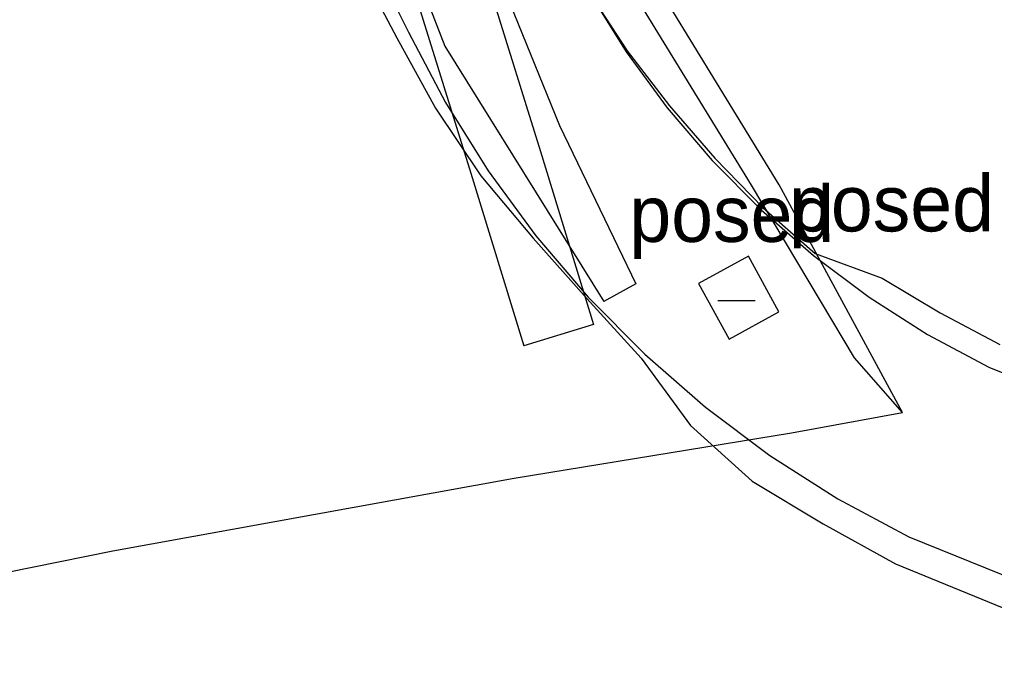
# Model space of a CAD drawing. Extents: x -475575 to -473225, y -1116053 to -1114104.
# Drawn here: x -474375.12 to -474349.11, y -1115076.37 to -1115059.4 of the extents above; entities that cross this region are included whole.
import ezdxf

# ---------------------------------------------------------------- set-up
doc = ezdxf.new("R2010")
doc.units = 0
for name, color, linetype in [('CESTN___P____KOP_N__VRH', 7, 'Continuous'), ('SVK', 7, 'Continuous'), ('Vrstevnice_vedlejsi', 7, 'Continuous'), ('Vrstva_10', 7, 'Continuous')]:
    doc.layers.add(name, color=color, linetype=linetype)

msp = doc.modelspace()

# ---------------------------------------------------------------- linework, layer by layer
at = {"layer": 'CESTN___P____KOP_N__VRH'}
for p, q in [((-474365.634, -1115057.941), (-474364.745, -1115059.732)), ((-474365.981, -1115058.113), (-474365.056, -1115059.887)), ((-474365.056, -1115059.887), (-474364.018, -1115061.759)), ((-474364.745, -1115059.732), (-474363.754, -1115061.607)), ((-474363.754, -1115061.607), (-474362.615, -1115063.428)), ((-474364.018, -1115061.759), (-474362.812, -1115063.561)), ((-474362.615, -1115063.428), (-474361.345, -1115065.16)), ((-474362.812, -1115063.561), (-474361.419, -1115065.219)), ((-474361.419, -1115065.219), (-474359.987, -1115066.828)), ((-474361.345, -1115065.16), (-474359.951, -1115066.794)), ((-474359.987, -1115066.828), (-474358.532, -1115068.419)), ((-474359.951, -1115066.794), (-474358.439, -1115068.319)), ((-474358.532, -1115068.419), (-474357.214, -1115070.218)), ((-474358.439, -1115068.319), (-474356.818, -1115069.728)), ((-474356.818, -1115069.728), (-474355.098, -1115071.014)), ((-474357.214, -1115070.218), (-474355.571, -1115071.699)), ((-474355.098, -1115071.014), (-474353.287, -1115072.169)), ((-474355.571, -1115071.699), (-474353.678, -1115072.835)), ((-474353.287, -1115072.169), (-474351.396, -1115073.186)), ((-474353.678, -1115072.835), (-474351.747, -1115073.901)), ((-474351.396, -1115073.186), (-474347.414, -1115074.789)), ((-474351.747, -1115073.901), (-474347.664, -1115075.573))]:
    msp.add_line(p, q, dxfattribs=at)
for points in [[(-474359.916, -1115058.683), (-474358.934, -1115060.253)], [(-474359.911, -1115058.681), (-474358.905, -1115060.233)], [(-474358.934, -1115060.253), (-474357.839, -1115061.746)], [(-474358.905, -1115060.233), (-474357.777, -1115061.696)], [(-474357.777, -1115061.696), (-474356.565, -1115063.088)], [(-474357.839, -1115061.746), (-474356.637, -1115063.154)], [(-474356.637, -1115063.154), (-474355.334, -1115064.469)], [(-474356.565, -1115063.088), (-474355.282, -1115064.414)], [(-474355.334, -1115064.469), (-474353.937, -1115065.684)], [(-474355.282, -1115064.414), (-474353.892, -1115065.629)], [(-474353.937, -1115065.684), (-474352.454, -1115066.792)], [(-474353.892, -1115065.629), (-474352.105, -1115066.287)], [(-474352.105, -1115066.287), (-474350.555, -1115067.212)], [(-474352.454, -1115066.792), (-474350.893, -1115067.788)], [(-474350.555, -1115067.212), (-474348.962, -1115068.053)], [(-474350.893, -1115067.788), (-474349.262, -1115068.665)], [(-474349.262, -1115068.665), (-474345.829, -1115070.046)]]:
    msp.add_lwpolyline(points, dxfattribs=at)
at = {"layer": 'SVK'}
msp.add_line((-474356.492, -1115066.882), (-474355.492, -1115066.882), dxfattribs=at)
for points in [[(-474531.417, -1114949.964), (-474518.735, -1114954.223), (-474505.508, -1114958.773), (-474490.04, -1114963.316), (-474478.285, -1114966.016), (-474465.065, -1114968.999), (-474452.484, -1114971.31), (-474438.955, -1114973.279), (-474425.793, -1114974.806), (-474414.372, -1114976.092), (-474408.245, -1114977.467), (-474402.318, -1114980.411), (-474397.56, -1114985.161), (-474394.659, -1114990.262), (-474387.875, -1115004.966), (-474382.653, -1115016.529), (-474372.424, -1115037.125), (-474369.444, -1115043.04), (-474363.811, -1115054.608), (-474360.711, -1115062.22), (-474358.674, -1115066.438), (-474359.526, -1115066.91)], [(-474532.059, -1114951.8), (-474519.359, -1114956.065), (-474506.097, -1114960.627), (-474490.531, -1114965.199), (-474478.715, -1114967.913), (-474465.454, -1114970.905), (-474452.799, -1114973.23), (-474439.207, -1114975.208), (-474426.014, -1114976.739), (-474414.695, -1114978.013), (-474408.9, -1114979.313), (-474403.467, -1114982.012), (-474399.12, -1114986.352), (-474396.39, -1114991.152), (-474389.644, -1115005.774), (-474384.41, -1115017.362), (-474374.163, -1115037.995), (-474371.187, -1115043.903), (-474365.624, -1115055.327), (-474363.775, -1115060.104), (-474359.526, -1115066.91)], [(-474354.522, -1115070.413), (-474351.56, -1115069.868), (-474354.851, -1115063.802), (-474360.04, -1115055.335), (-474366.606, -1115042.832), (-474370.618, -1115035.13), (-474372.803, -1115030.873)], [(-474351.56, -1115069.868), (-474352.844, -1115068.409), (-474355.586, -1115063.813), (-474358.809, -1115058.557), (-474361.838, -1115053.994), (-474365.362, -1115048.002), (-474368.068, -1115042.4), (-474370.949, -1115037.299), (-474373.878, -1115031.38)], [(-474456.608, -1115092.439), (-474444.222, -1115089.576), (-474432.477, -1115086.843), (-474420.046, -1115083.62), (-474408.267, -1115081.299), (-474394.218, -1115078.309), (-474384.628, -1115075.984), (-474372.626, -1115073.554), (-474361.918, -1115071.619), (-474354.522, -1115070.413)]]:
    msp.add_lwpolyline(points, dxfattribs=at)
msp.add_lwpolyline([(-474354.857, -1115067.189), (-474355.671, -1115065.704), (-474357.002, -1115066.433), (-474356.187, -1115067.919)], close=True, dxfattribs=at)
at = {"layer": 'Vrstevnice_vedlejsi'}
for points in [[(-474227.218, -1115164.851), (-474226.448, -1115162.426), (-474227.525, -1115159.571), (-474230.451, -1115156.287), (-474235.226, -1115152.573), (-474240.399, -1115148.881), (-474245.971, -1115145.211), (-474251.942, -1115141.562), (-474256.818, -1115137.139), (-474260.6, -1115131.942), (-474263.287, -1115125.971), (-474265.918, -1115121.36), (-474268.492, -1115118.11), (-474271.011, -1115116.221), (-474273.409, -1115112.993), (-474275.686, -1115108.429), (-474277.843, -1115102.526), (-474279.974, -1115096.744), (-474282.078, -1115091.082), (-474284.156, -1115085.541), (-474285.812, -1115080.883), (-474287.047, -1115077.109), (-474287.86, -1115074.218), (-474288.244, -1115068.81), (-474288.198, -1115060.885), (-474287.724, -1115050.442), (-474287.488, -1115042.595), (-474287.491, -1115037.342), (-474287.732, -1115034.684), (-474288.91, -1115029.354), (-474291.024, -1115021.351), (-474294.074, -1115010.675), (-474297.009, -1115000.754), (-474299.828, -1114991.588), (-474302.532, -1114983.176), (-474304.676, -1114975.928), (-474306.261, -1114969.843), (-474307.286, -1114964.921), (-474309.265, -1114957.199), (-474312.198, -1114946.677), (-474316.084, -1114933.354), (-474318.675, -1114924.468), (-474319.971, -1114920.02), (-474319.973, -1114920.01), (-474319.977, -1114919.992), (-474319.984, -1114919.965), (-474319.992, -1114919.931), (-474321.301, -1114916.779), (-474323.911, -1114910.509), (-474327.823, -1114901.121), (-474333.571, -1114893.897), (-474341.156, -1114888.835), (-474350.578, -1114885.936), (-474361.246, -1114883.666), (-474373.16, -1114882.025), (-474386.32, -1114881.012), (-474395.152, -1114880.336), (-474399.654, -1114879.994), (-474399.827, -1114879.989), (-474403.877, -1114879.477), (-474411.805, -1114878.46), (-474423.609, -1114876.937), (-474431.988, -1114875.62), (-474436.942, -1114874.51), (-474438.471, -1114873.607), (-474443.932, -1114869.371), (-474453.324, -1114861.802), (-474466.647, -1114850.901), (-474475.533, -1114843.63), (-474479.981, -1114839.989), (-474479.99, -1114839.978), (-474480.008, -1114839.975), (-474480.035, -1114839.978), (-474480.069, -1114839.989), (-474480.092, -1114840.008), (-474480.104, -1114840.035), (-474480.104, -1114840.069), (-474483.152, -1114844.525), (-474489.247, -1114853.403), (-474498.39, -1114866.701), (-474505.505, -1114879.646), (-474510.592, -1114892.237), (-474513.651, -1114904.473), (-474515.798, -1114912.997), (-474517.033, -1114917.807), (-474517.355, -1114918.903), (-474517.71, -1114919.879), (-474518.097, -1114920.733), (-474518.517, -1114921.467), (-474518.841, -1114922.054), (-474519.069, -1114922.494), (-474519.202, -1114922.788), (-474519.513, -1114923.611), (-474520.002, -1114924.961), (-474520.669, -1114926.839), (-474521.912, -1114930.34), (-474523.73, -1114935.464)], [(-474354.105, -1114959.425), (-474354.101, -1114959.005), (-474354.186, -1114958.537), (-474354.359, -1114958.023), (-474354.62, -1114957.461), (-474355.156, -1114956.331), (-474355.969, -1114954.634), (-474357.058, -1114952.369), (-474357.853, -1114950.758), (-474358.355, -1114949.8), (-474358.564, -1114949.496), (-474359.02, -1114949.288), (-474359.724, -1114949.176), (-474360.675, -1114949.161), (-474363.079, -1114948.002), (-474366.934, -1114945.701), (-474372.241, -1114942.257), (-474378.274, -1114938.663), (-474385.032, -1114934.919), (-474392.516, -1114931.025), (-474401.95, -1114928.025), (-474413.333, -1114925.919), (-474426.667, -1114924.707), (-474439.186, -1114927.544), (-474450.893, -1114934.43), (-474461.786, -1114945.365), (-474469.453, -1114952.769), (-474473.895, -1114956.641), (-474475.111, -1114956.983), (-474476.002, -1114957.247), (-474476.567, -1114957.432), (-474476.807, -1114957.54), (-474477.184, -1114957.779), (-474477.698, -1114958.149), (-474478.349, -1114958.649), (-474479.36, -1114959.359), (-474480.73, -1114960.28), (-474482.46, -1114961.41), (-474483.648, -1114962.287), (-474484.295, -1114962.912), (-474484.4, -1114963.284), (-474484.645, -1114963.595), (-474485.031, -1114963.846), (-474485.557, -1114964.035), (-474485.898, -1114964.243), (-474486.055, -1114964.469), (-474486.027, -1114964.712), (-474485.995, -1114965.021), (-474485.958, -1114965.394), (-474485.917, -1114965.831), (-474486.054, -1114967.207), (-474486.37, -1114969.521), (-474486.864, -1114972.774), (-474487.546, -1114977.662), (-474488.415, -1114984.186), (-474489.472, -1114992.346), (-474491.855, -1115000.601), (-474495.567, -1115008.951), (-474500.606, -1115017.397), (-474504.68, -1115024.6), (-474507.789, -1115030.562), (-474509.934, -1115035.281), (-474512.243, -1115039.307), (-474514.719, -1115042.641), (-474517.359, -1115045.281), (-474520.545, -1115049.18), (-474524.277, -1115054.338), (-474528.554, -1115060.753), (-474532.831, -1115066.456), (-474537.108, -1115071.446), (-474541.385, -1115075.723), (-474544.815, -1115079.567), (-474547.398, -1115082.979), (-474549.134, -1115085.958), (-474550.675, -1115088.312), (-474552.021, -1115090.041), (-474553.172, -1115091.145), (-474554.57, -1115092.417), (-474556.215, -1115093.856), (-474558.108, -1115095.462), (-474561.095, -1115099.081), (-474565.178, -1115104.712), (-474570.356, -1115112.356), (-474574.482, -1115118.681), (-474577.557, -1115123.686), (-474579.579, -1115127.373), (-474581.379, -1115130.995), (-474582.955, -1115134.554), (-474584.307, -1115138.048), (-474585.803, -1115141.365), (-474587.442, -1115144.503), (-474589.225, -1115147.463), (-474590.455, -1115149.735), (-474591.131, -1115151.32), (-474591.255, -1115152.218), (-474591.591, -1115153.581), (-474592.14, -1115155.41)], [(-474562.814, -1115258.883), (-474556.566, -1115263.192), (-474554.007, -1115264.854), (-474552.014, -1115266.022), (-474550.587, -1115266.697), (-474546.782, -1115268.03), (-474540.601, -1115270.021), (-474532.042, -1115272.67), (-474525.912, -1115274.571), (-474522.211, -1115275.726), (-474520.939, -1115276.133), (-474519.16, -1115276.789), (-474516.873, -1115277.693), (-474514.079, -1115278.847), (-474509.857, -1115280.733), (-474504.208, -1115283.352), (-474497.132, -1115286.704), (-474491.297, -1115289.181), (-474486.704, -1115290.784), (-474483.352, -1115291.513), (-474479.959, -1115291.797), (-474476.524, -1115291.637), (-474473.048, -1115291.033), (-474467.445, -1115290.367), (-474459.715, -1115289.64), (-474449.857, -1115288.851), (-474440.797, -1115287.429), (-474432.535, -1115285.375), (-474425.07, -1115282.687), (-474415.679, -1115278.909), (-474404.362, -1115274.041), (-474391.12, -1115268.082), (-474380.305, -1115262.495), (-474371.918, -1115257.281), (-474365.959, -1115252.439), (-474360.859, -1115248.375), (-474356.619, -1115245.087), (-474353.238, -1115242.577), (-474347.667, -1115236.471), (-474339.905, -1115226.77), (-474329.952, -1115213.472), (-474323.31, -1115204.595), (-474319.977, -1115200.139), (-474319.955, -1115200.103), (-474319.933, -1115200.072), (-474319.912, -1115200.045), (-474319.891, -1115200.023), (-474319.876, -1115199.987), (-474319.868, -1115199.938), (-474319.866, -1115199.877), (-474319.662, -1115198.394), (-474319.256, -1115195.49), (-474318.648, -1115191.166), (-474317.588, -1115187.324), (-474316.077, -1115183.964), (-474314.115, -1115181.088), (-474311.694, -1115177.146), (-474308.814, -1115172.14), (-474305.475, -1115166.07), (-474303.741, -1115159.072), (-474303.611, -1115151.146), (-474305.087, -1115142.291), (-474306.631, -1115134.896), (-474308.242, -1115128.958), (-474309.922, -1115124.479), (-474311.744, -1115117.279), (-474313.709, -1115107.359), (-474315.815, -1115094.719), (-474317.306, -1115086.061), (-474318.182, -1115081.385), (-474318.442, -1115080.693), (-474318.759, -1115079.718), (-474319.134, -1115078.461), (-474319.567, -1115076.922), (-474321.065, -1115073.108), (-474323.627, -1115067.021), (-474327.254, -1115058.659), (-474329.677, -1115052.77), (-474330.897, -1115049.353), (-474330.912, -1115048.408), (-474331.035, -1115047.457), (-474331.266, -1115046.5), (-474331.605, -1115045.537), (-474332.715, -1115044.387), (-474334.597, -1115043.05), (-474337.25, -1115041.525), (-474339.266, -1115038.523), (-474340.647, -1115034.045), (-474341.391, -1115028.09), (-474342.59, -1115021.661), (-474344.244, -1115014.757), (-474346.352, -1115007.379), (-474348.385, -1114997.998), (-474350.343, -1114986.615), (-474352.226, -1114973.23), (-474353.48, -1114964.167), (-474354.105, -1114959.425)]]:
    msp.add_spline(points, degree=3, dxfattribs=at)
at = {"layer": 'Vrstva_10'}
msp.add_line((-474356.492, -1115066.882), (-474355.492, -1115066.882), dxfattribs=at)
for points in [[(-474531.417, -1114949.964), (-474518.735, -1114954.223), (-474505.508, -1114958.773), (-474490.04, -1114963.316), (-474478.285, -1114966.016), (-474465.065, -1114968.999), (-474452.484, -1114971.31), (-474438.955, -1114973.279), (-474425.793, -1114974.806), (-474414.372, -1114976.092), (-474408.245, -1114977.467), (-474402.318, -1114980.411), (-474397.56, -1114985.161), (-474394.659, -1114990.262), (-474387.875, -1115004.966), (-474382.653, -1115016.529), (-474372.424, -1115037.125), (-474369.444, -1115043.04), (-474363.811, -1115054.608), (-474361.222, -1115062.915), (-474359.802, -1115067.52), (-474361.66, -1115068.093)], [(-474532.059, -1114951.8), (-474519.359, -1114956.065), (-474506.097, -1114960.627), (-474490.531, -1114965.199), (-474478.715, -1114967.913), (-474465.454, -1114970.905), (-474452.799, -1114973.23), (-474439.207, -1114975.208), (-474426.014, -1114976.739), (-474414.695, -1114978.013), (-474408.9, -1114979.313), (-474403.467, -1114982.012), (-474399.12, -1114986.352), (-474396.39, -1114991.152), (-474389.644, -1115005.774), (-474384.41, -1115017.362), (-474374.163, -1115037.995), (-474371.187, -1115043.903), (-474365.624, -1115055.327), (-474363.079, -1115063.491), (-474361.66, -1115068.093)], [(-474354.522, -1115070.413), (-474351.56, -1115069.868), (-474354.851, -1115063.802), (-474360.04, -1115055.335), (-474366.606, -1115042.832), (-474370.618, -1115035.13), (-474372.803, -1115030.873)], [(-474351.56, -1115069.868), (-474352.844, -1115068.409), (-474355.586, -1115063.813), (-474358.809, -1115058.557), (-474361.838, -1115053.994), (-474365.362, -1115048.002), (-474368.068, -1115042.4), (-474370.949, -1115037.299), (-474373.878, -1115031.38)], [(-474456.608, -1115092.439), (-474444.222, -1115089.576), (-474432.477, -1115086.843), (-474420.046, -1115083.62), (-474408.267, -1115081.299), (-474394.218, -1115078.309), (-474384.628, -1115075.984), (-474372.626, -1115073.554), (-474361.918, -1115071.619), (-474354.522, -1115070.413)]]:
    msp.add_lwpolyline(points, dxfattribs=at)
msp.add_lwpolyline([(-474354.857, -1115067.189), (-474355.671, -1115065.704), (-474357.002, -1115066.433), (-474356.187, -1115067.919)], close=True, dxfattribs=at)

# ---------------------------------------------------------------- texts
at = {"layer": 'SVK'}
msp.add_text('posed', height=1.5, dxfattribs=at).set_placement((-474354.588, -1115065.043))
at = {"layer": 'Vrstva_10'}
msp.add_text('posed', height=1.5, dxfattribs=at).set_placement((-474358.848, -1115065.323))

doc.saveas('drawing.dxf')
